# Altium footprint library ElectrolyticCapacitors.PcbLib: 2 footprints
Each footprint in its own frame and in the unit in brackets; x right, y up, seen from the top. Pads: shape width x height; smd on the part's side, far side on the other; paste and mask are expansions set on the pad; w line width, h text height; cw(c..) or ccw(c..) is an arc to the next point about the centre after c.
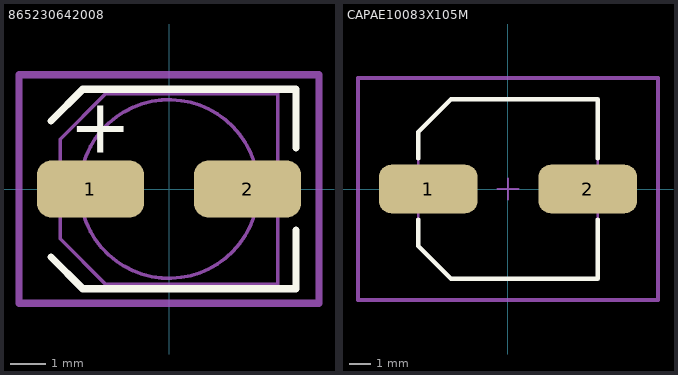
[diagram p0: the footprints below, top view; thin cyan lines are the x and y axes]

## 865230642008 [mm] "SMD Aluminium Electrolytic Capacitor, Radial Can - SMD, 4.7 µF, 50 V, 5000 hours @ 105°C, Polar"
height 0.14
pads (2):
  rrect50% 3x1.6 smd: 1(-2.2,0) 2(2.2,0)
Top Overlay:
  lines w0.2: -3.302,-1.905 -2.413,-2.794 3.556,-2.794 3.556,-2.667 3.556,-1.143 ; -3.302,1.905 -2.413,2.794 3.556,2.794 3.556,2.667 3.556,1.143
  text "+" at -2.794,1.016 h1.52
Mechanical 13 (Mech13):
  circle w0.1: c0,0 r2.5
  lines w0.1: -3.048,-1.397 -1.778,-2.667 3.048,-2.667 3.048,2.667 -1.778,2.667 -3.048,1.397 -3.048,-1.397
Component Courtyard:
  lines w0.2: -4.2,-3.2 4.2,-3.2 4.2,3.2 -4.2,3.2 -4.2,-3.2
3D body "Download_STP_865230x4200x (rev1).stp": height 5.35, standoff -0.15, extent -3,-2.65 3,2.65

## CAPAE10083X105M [mm] "Aluminum Electrolytic Capacitor, Body 8.30x8.30x10.50mm, IPC Low Density"
height 10.5
pads (2):
  rrect50% 4.65x2.3 smd: 1(-3.775,0) 2(3.775,0)
Top Overlay:
  lines w0.2: -4.25,-1.45 -4.25,-2.7 -2.7,-4.25 4.25,-4.25 4.25,-1.45 ; -4.25,1.45 -4.25,2.7 -2.7,4.25 4.25,4.25 4.25,1.45
Mechanical 13 (Mech13):
  lines w0.1: -4.25,-2.7 -4.25,2.7 -2.7,4.25 4.25,4.25 4.25,-4.25 -2.7,-4.25 -4.25,-2.7
Component Courtyard:
  lines w0.1: -0.5,0 0.5,0 ; 0,-0.5 0,0.5
  lines w0.2: -7.1,-5.25 7.1,-5.25 7.1,5.25 -7.1,5.25 -7.1,-5.25
3D body "CAPAE10083X105M.step": height 10.5, standoff 0, extent -5,-4.25 5,4.25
